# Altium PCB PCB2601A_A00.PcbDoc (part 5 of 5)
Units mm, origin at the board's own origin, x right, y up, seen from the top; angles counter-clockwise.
Board outline 30.4 x 51 mm, 8 copper layers (Top Layer, Signal Layer 2, Signal Layer 3, Signal Layer 4, Signal Layer 5, Signal Layer 6, Signal Layer 7, Bottom Layer), stack 1.492 mm thick; 194 components, 130 nets, 5039 pads, 478 vias.
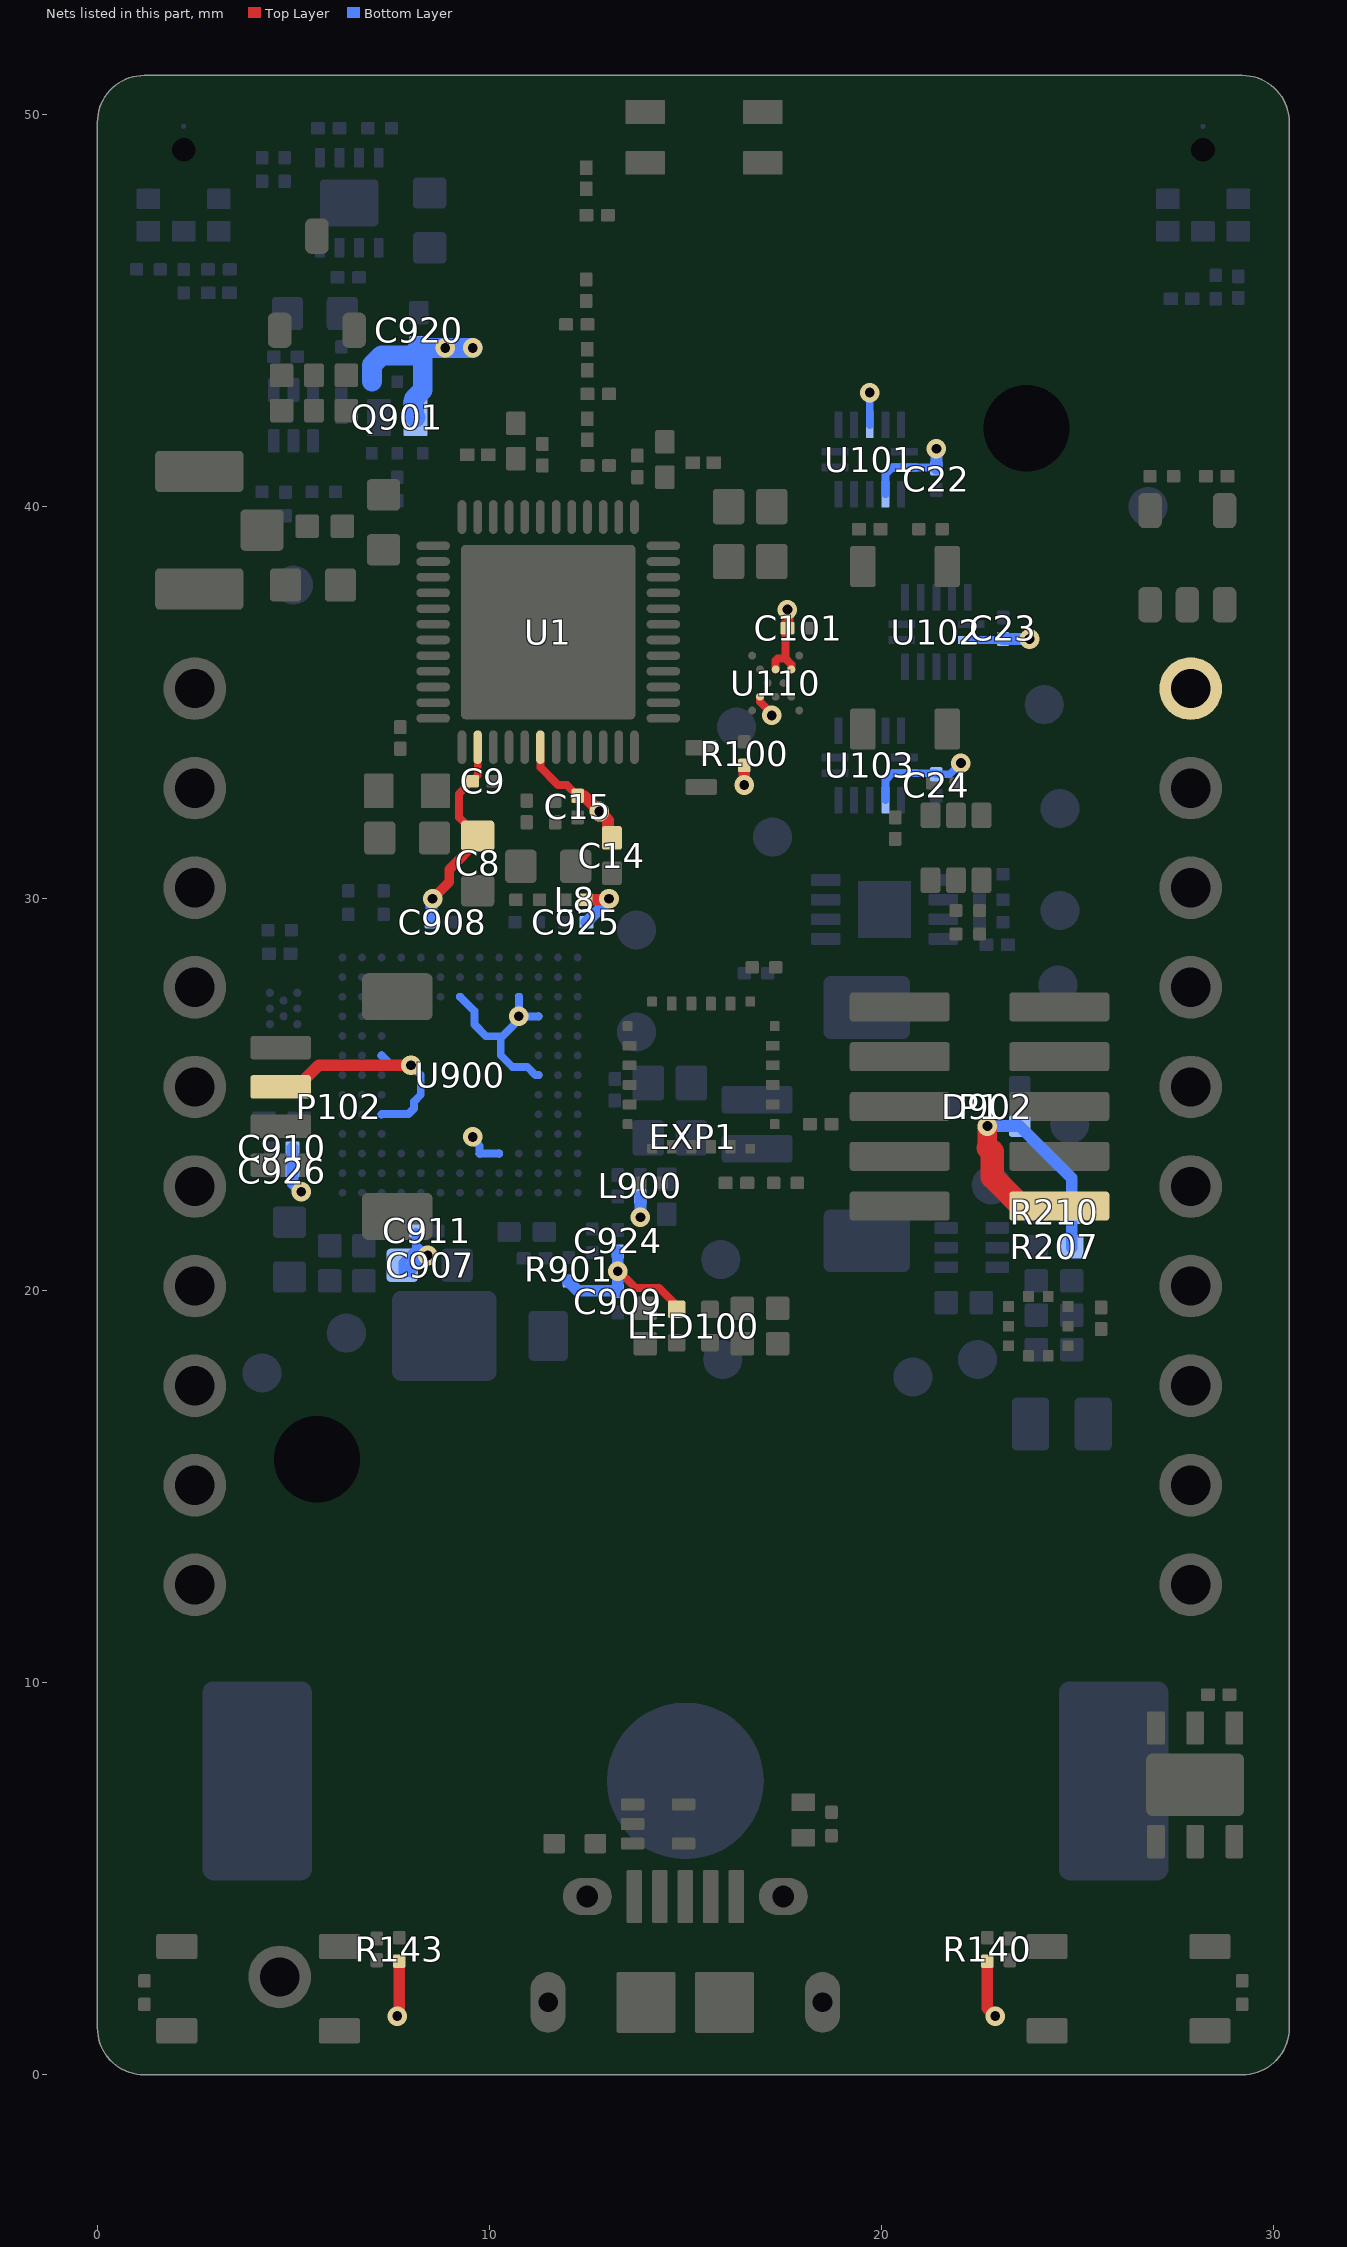
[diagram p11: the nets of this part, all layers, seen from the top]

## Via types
v1: diameter 0.5, hole 0.25, Top Layer to Bottom Layer, tented both sides, 478 vias

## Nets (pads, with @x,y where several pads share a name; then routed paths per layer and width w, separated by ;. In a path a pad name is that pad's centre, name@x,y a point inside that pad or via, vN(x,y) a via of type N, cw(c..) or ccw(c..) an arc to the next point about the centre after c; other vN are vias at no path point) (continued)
VMCU: C8.1 C9.1 C14.1 C15.1 C22.1 C23.1 C24.1 C101.1 C907.1 C908.1 C909.1 C910.1 C911.1 C920.1 C924.1 C925.1 C926.1 D902.2 EXP1.2 L8.1 L900.1 LED100.1 P1.1 P102.2 Q901.4 Q901.6 Q901.7 R100.1 R140.1 R143.1 R207.2 R210.2 R901.2 U1.38 U1.42 U101.2 U101.10 U101.14 U102.14 U103.2 U103.14 U110.B2 U110.D2 U110.F4 U900.C6 U900.C9 U900.G3 U900.H11 U900.J11 U900.K3 U900.L4 U900.L7 | length 58.6
  Top Layer w0.2: C8.1@9.7,31.6 9.225,32.075 9.225,32.675 C9.1@9.55,33 9.7,33.15 U1.38@9.7,33.865 ; U1.42@11.3,33.865 11.3,33.35 11.75,32.9 11.975,32.9 C15.1@12.25,32.625 ; v1@13.4,20.4 13.725,20.075 14.323,20.075 14.775,19.623 LED100.1@14.775,19.525 ; U110.F4@16.9,35.15 16.9,35.025 17.2,34.725 v1(17.2,34.675) ; U110.D2@17.3,35.85 17.3,36.075 17.35,36.125 17.55,36.125 ; C101.1@17.6,36.9 17.55,36.85 17.55,36.125 ; U110.B2@17.7,35.85 17.7,35.975 17.55,36.125
  Top Layer w0.25: v1(8.55,30) 8.975,30.425 8.975,30.75 9.7,31.475 C8.1@9.7,31.6
  Top Layer w0.3: P102.2@4.675,25.2 5.1,25.2 5.65,25.75 v1(8,25.75) ; v1(7.65,1.5) 7.7,1.55 R143.1@7.7,2.9 ; C15.1@12.25,32.625 12.4,32.625 v1(12.8,32.225) 13.025,32 13.025,31.65 C14.1@13.125,31.55 ; L8.1@12.445,29.975 13.025,29.975 v1(13.05,30) ; v1(16.5,32.9) R100.1@16.5,33.4 ; C101.1@17.6,36.9 v1(17.6,37.375) ; R140.1@22.7,2.9 22.7,1.7 v1(22.9,1.5)
  Top Layer w0.5: v1(22.7,24.2) 22.7,23.675 22.725,23.65
  Top Layer w0.6: 22.725,23.65 22.825,23.55 22.825,22.9 23.565,22.16 P1.1@24.535,22.16
  Bottom Layer w0.2: U900.C9@7.25,24.5 7.26,24.51 7.935,24.51 8.075,24.65 8.075,24.825 8.25,25 8.25,25.5 v1(8,25.75) 7.5,25.75 U900.C6@7.25,26 ; C907.1@8.125,20.825 8.125,21.075 ; C911.1@8.125,21.5 8.125,21.175 ; U900.G3@9.25,27.5 9.617,27.133 9.617,26.79 9.915,26.492 10.335,26.492 ; v1(9.575,23.925) 9.575,23.87 9.75,23.695 U900.H11@9.75,23.5 U900.J11@10.25,23.5 ; U900.K3@10.75,27.5 v1(10.75,27) ; U900.L7@11.25,25.5 11.175,25.5 10.964,25.712 10.584,25.712 10.287,26.009 10.287,26.443 10.335,26.492 ; U900.L4@11.25,27 v1(10.75,27) ; U101.10@19.7,42.085 v1(19.7,42.91) ; U103.2@20.1,32.515 20.1,33.025 20.275,33.2 U103.14@20.585,33.2 21.375,33.2 C24.1@21.4,33.175 21.741,33.175 v1(22.026,33.46) 22.011,33.475 22,33.475 v1@21.9,33.375 ; U101.2@20.1,40.315 20.1,40.825 20.275,41 U101.14@20.585,41 21.375,41 C22.1@21.4,40.975 ; U102.14@22.285,36.6 23.075,36.6 C23.1@23.1,36.625 ; C907.1@7.775,20.45 7.775,20.725 8.125,21.075 ; C907.1@7.775,20.45 7.975,20.45 v1(8.425,20.9) v1@8.4,20.9 ; C907.1@7.775,20.45 8.225,20.9 v1@8.4,20.9 ; 8.125,21.075 8.125,21.175 ; 8.125,21.175 v1@8.4,20.9 ; 10.335,26.492 10.633,26.79 10.633,26.883 v1(10.75,27)
  Bottom Layer w0.3: C910.1@4.975,23.65 C926.1@4.975,23.05 4.975,22.75 v1(5.2,22.525) ; C908.1@8.525,29.4 8.525,29.975 v1(8.55,30) ; R901.2@12,20.25 12.25,20 C909.1@13.275,20 v1(13.275,20.5) C924.1@13.275,21 ; C925.1@12.475,29.4 13.05,29.975 v1(13.05,30) ; v1(13.85,21.875) L900.1@13.85,22.405 ; C22.1@21.4,40.975 v1(21.4,41.475) v1@21.4,41.479 ; v1(22.7,24.2) D902.2@23.525,24.2 24.85,22.875 R210.2@24.85,22 24.85,21.95 R207.2@24.85,21.125 R207.2@24.85,21.1 ; C23.1@23.1,36.625 v1@23.604,36.625
  Bottom Layer w0.305: C909.1@13.275,19.98 C909.1@13.278,19.983
  Bottom Layer w0.508: Q901.4@7,43.188 7,43.608 7.242,43.85 8,43.85 C920.1@8.2,44.05 ; Q901.7@8.116,42.275 8.075,42.316 8.075,42.75 8.3,42.975 Q901.6@8.3,43.188 8.3,43.908 C920.1@8.2,44.008 ; C920.1@8.2,44.092 C920.1@8.2,44.05 ; v1(9.575,44.05) v1(8.875,44.05) C920.1@8.2,44.05
  other v1: 23.775,36.625
pads on no net: D101.3 D900.1 LOGO_SEGGER.1 M900.7 M900.9 M901.1 M902.1 P102.5 P102.6 P900.4 U104.1 U104.2 U104.3 U104.4 U104.5 U104.6 U104.7 U104.14 U104.15 U104.16 U104.17 U104.19 U104.20 U104.21 U105.4 U108.3 U108.4 U108.7 U110.A1 U110.A5 U110.G1 U110.G5 U111.H1 U112.H1 U900.A7 U900.B4 U900.B5 U900.B6 U900.B7 U900.B8 U900.B9 U900.B11 U900.C4 U900.C7 U900.D2 U900.D13 U900.E2 U900.E11 U900.E12 U900.E13 U900.F1 U900.F2 U900.F3 U900.F11 U900.F12 U900.G1 U900.G2 U900.G12 U900.H1 U900.H2 U900.J1 U900.J2 U900.K1 U900.K2 U900.K13 U900.L3 U900.L11 U900.L12 U900.L13 U900.M2 U900.M3 U900.M4 U900.M5 U900.M6 U900.M12 U900.M13 U900.N3 U900.N4 U900.N5 U900.N6 U900.N7 U901.C1 U902.8 U903.9

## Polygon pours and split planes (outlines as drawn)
GND on Top Layer "GND_L01_P047" (solid, remove dead copper, pour order 47): 0,0 0,51 30.4,51 30.403,0
GND on Bottom Layer "GND_L08_P053" (solid, remove dead copper, pour order 53): 0,0 0,51 30.4,51 30.403,0
VMCU on Signal Layer 7 "VMCU_L07_P052" (solid, remove dead copper, pour order 52): 0,0 0,51 30.4,51 30.403,0
GND on Signal Layer 6 "GND_L06_P051" (solid, remove dead copper, pour order 51): 0,0 0,51 30.4,51 30.403,0
GND on Signal Layer 5 "GND_L05_P050" (solid, remove dead copper, pour order 50): 0,0 0,51 30.4,51 30.403,0
GND on Signal Layer 4 "GND_L04_P049" (solid, remove dead copper, pour order 49): 0,0 0,51 30.4,51 30.403,0
GND on Signal Layer 3 "GND_L03_P048" (solid, remove dead copper, pour order 48): 0,0 0,51 30.4,51 30.403,0
GND on Signal Layer 2 "GND_L02_P024" (solid, remove dead copper, pour order 24): 0,0 0,51 30.4,51 30.403,0

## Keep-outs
Top Layer:
  circle w0.05: c5.6,15.7 r3
  circle w0.05: c23.7,42 r3
Bottom Layer:
  circle w0.1: c26.05,22 r0.5
  circle w0.1: c23.65,26.75 r0.5
  circle w0.1: c17.22,29.05 r0.5
  circle w0.1: c14.69,31.53 r0.5
  circle w0.1: c13.8,33.9 r0.5
  circle w0.1: c1.54,10.95 r0.5
  circle w0.1: c22.045,42.635 r0.3

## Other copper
Top Layer:
  pour cut-out: 13.876,42.87 ccw(c13.482,42.87) 13.482,43.264 ccw(c13.482,42.87) 13.089,42.87 ccw(c13.482,42.87) 13.482,42.477 ccw(c13.482,42.87)
  pour cut-out: 13.526,43.245 ccw(c13.132,43.245) 13.132,43.639 ccw(c13.132,43.245) 12.738,43.245 ccw(c13.132,43.245) 13.132,42.851 ccw(c13.132,43.245)
  pour cut-out: 13.526,42.495 ccw(c13.132,42.495) 13.132,42.889 ccw(c13.132,42.495) 12.738,42.495 ccw(c13.132,42.495) 13.132,42.101 ccw(c13.132,42.495)
  pour cut-out: 11.021,44.699 ccw(c11.414,44.699) 11.414,44.306 ccw(c11.414,44.699) 11.808,44.699 ccw(c11.414,44.699) 11.414,45.093 ccw(c11.414,44.699)
  pour cut-out: 11.404,44.32 ccw(c11.797,44.32) 11.797,43.927 ccw(c11.797,44.32) 12.191,44.32 ccw(c11.797,44.32) 11.797,44.714 ccw(c11.797,44.32)
  pour cut-out: 11.413,44.994 ccw(c11.807,44.994) 11.807,44.601 ccw(c11.807,44.994) 12.201,44.994 ccw(c11.807,44.994) 11.807,45.388 ccw(c11.807,44.994)
  pour cut-out: 8.5,34.8 8.5,33.9 7.9,33.3 6.6,33.3 6.6,31.096 9.325,31.096 9.325,34.8
  pour cut-out: 13.7,34.8 16.2,34.8 16.2,32.4 13.712,32.4 13.712,34.496
  region net N17172364: 8.25,32.5 8.25,33.275 9.25,34.275 9.325,34.275 9.4,34.2 9.4,33.5 9,33.1 9,32.5
  pour cut-out: 13.425,39.8 11.8,39.8 11.8,41.984 12.009,42.193 12.009,46.1 12.916,46.1 12.992,46.023 12.992,41.958 13.075,41.875 13.3,41.875 13.425,41.75
  pour cut-out: 16.35,40.55 18.3,40.55 18.3,39.9 17.805,39.405 17.806,37.94 14.6,37.94 14.6,38.8
  region net GND: 13.472,50.404 12.85,50.404 12.85,49.579 13.472,49.579
Bottom Layer:
  pour cut-out: 17.907,1.563 17.907,2.148 cw(c18.489,2.148) 18.489,2.731 cw(c18.489,2.15) 19.07,2.15 19.07,1.5 cw(c18.52,1.5) 18.52,0.95 cw(c18.52,1.563)
  pour cut-out: 10.907,1.563 10.907,2.148 cw(c11.489,2.148) 11.489,2.731 cw(c11.489,2.15) 12.07,2.15 12.07,1.5 cw(c11.52,1.5) 11.52,0.95 cw(c11.52,1.563)
  pour cut-out: 16.745,4.55 cw(c17.345,4.55) 17.345,5.15 17.645,5.15 cw(c17.645,4.55) 18.245,4.55 cw(c17.645,4.55) 17.645,3.95 17.345,3.95 cw(c17.345,4.55)
  pour cut-out: 11.745,4.55 cw(c12.345,4.55) 12.345,5.15 12.645,5.15 cw(c12.645,4.55) 13.245,4.55 cw(c12.645,4.55) 12.645,3.95 12.345,3.95 cw(c12.345,4.55)
  pour cut-out: 5.784,22.1 12.7,22.1 12.7,28.9 5.833,28.9
  pour cut-out: 7.75,45.65 7.975,45.65 7.975,45.15 7.75,45.15
  pour cut-out: 4.4,20.95 4.4,21.85 5.35,21.85 5.35,20.95
Multi-Layer:
  pour cut-out: 23,4.9 23,10.2 cw(c24.5,10.2) 24.5,11.7 31.3,11.7 31.3,3.4 24.5,3.4 cw(c24.5,4.9)
  pour cut-out: 17.475,51 17.475,44.4 13.475,44.4 13.475,51

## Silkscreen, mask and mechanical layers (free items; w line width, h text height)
Top Overlay:
  the board outline again, w0.1
Bottom Overlay:
  the board outline again, w0.1
Top Solder:
  the board outline again, w0.8
Bottom Solder:
  the board outline again, w0.8
BOARD OUTLINE 1:
  lines w0.1: 0,16.5 ccw(c-1.2,16.5) -2.4,16.5 -2.4,1.2 ccw(c1.2,1.2) 1.2,-2.4 29.2,-2.4 ccw(c29.2,1.2) 32.8,1.2 32.8,16.5 ccw(c31.6,16.5) 30.4,16.5 ; 0,28.5 cw(c-1.2,28.5) -2.4,28.5 -2.4,49.8 cw(c1.2,49.8) 1.2,53.4 9.21,53.4 cw(c9.21,52.2) 9.21,51 ; 21.19,51 cw(c21.19,52.2) 21.19,53.4 29.2,53.4 cw(c29.2,49.8) 32.8,49.8 32.8,28.499 ; 30.4,28.5 ccw(c31.6,28.5) 32.8,28.5 ; 0,1.2 ccw(c1.2,1.2) 1.2,0 29.2,0 ccw(c29.2,1.2) 30.4,1.2 30.4,49.8 ccw(c29.2,49.8) 29.2,51 1.2,51 ccw(c1.2,49.8) 0,49.8 0,1.2 ; 23.4,5.3 ccw(c23.8,5.3) 23.8,4.9 ccw(c23.8,5.3) 24.2,5.3 24.2,9.8 ccw(c23.8,9.8) 23.8,10.2 ccw(c23.788,9.812) 23.4,9.825 23.4,5.3 ; 25.2,4.3 ccw(c25.588,4.288) 25.575,3.9 29.2,3.9 ccw(c29.2,4.3) 29.6,4.3 ccw(c29.2,4.3) 29.2,4.7 25.6,4.7 ccw(c25.6,4.3) 25.2,4.3 ; 25.2,10.8 cw(c25.6,10.8) 25.6,11.2 29.2,11.2 cw(c29.2,10.8) 29.6,10.8 cw(c29.2,10.8) 29.2,10.4 25.575,10.4 cw(c25.588,10.788) 25.2,10.8
  text "Milling 0.8 mm (3 pcs)" at 14.6,2.7 h0.76
Mechanical 2:
  lines w0.1: 0,1.2 ccw(c1.2,1.2) 1.2,0 29.2,0 ccw(c29.2,1.2) 30.4,1.2 30.4,47.8 ccw(c29.2,47.8) 29.2,49 1.2,49 ccw(c1.2,47.8) 0,47.8 0,1.2
Mechanical 3:
  the board outline again, w0.1
Mechanical 15:
  lines w0.1: -0.5,0 0.5,0 ; 0,-0.5 0,0.5
Top EXT_SILKP 21/EXT_SILKS 22:
  text "ADC" at 1.424,42.194 h1.27
  text "1" at 0.7,34.885 h1.5
  text "2" at 29,34.86 h1.5
  text "RESET" at 23.306,34.566 h1.27 r90
  text "3" at 0.7,32.335 h1.5
  text "4" at 29,32.312 h1.5
  text "5" at 0.7,29.76 h1.5
  text "6" at 29,29.772 h1.5
  text "EFR32MG24" at 6.319,28.411 h2
  text "8" at 29,27.235 h1.5
  text "7" at 0.7,27.21 h1.5
  text "9" at 0.7,24.735 h1.5
  text "10" at 28.7,24.735 h1.5
  text "12" at 28.7,22.21 h1.5
  text "11" at 0.425,22.135 h1.5
  text "2" at 19.961,20.793 h1.27
  text "1" at 24.15,20.793 h1.27
  text "14" at 28.7,19.635 h1.5
  text "13" at 0.4,19.56 h1.5
  text "16" at 28.7,17.11 h1.5
  text "LED0" at 13.85,17.099 h1.27
  text "15" at 0.4,17.06 h1.5
  text "18" at 28.725,14.56 h1.5
  text "17" at 0.4,14.51 h1.5
  text "20" at 28.625,12.06 h1.5
  text "19" at 0.4,12.01 h1.5
  text "J-Link" at 16.504,7.601 h1.27
  text "BTN1" at 6.896,1.793 h1.27
  text "BTN0" at 20.819,1.799 h1.27
Bottom EXT_SILKP 21/EXT_SILKS 22:
  circle w0.152: c4.65,2.5 r0.966
  lines w0.152: 11,45.235 11,44.235 12,44.235 ; 11,47.285 11,48.285 12,48.285 ; 20.5,44.235 21.5,44.235 21.5,45.235 ; 20.5,48.285 21.5,48.285 21.5,47.285
  text "PCB2601A Rev A00" at 28.975,11.5 h1.5 r270
Mechanical 26:
  lines w0.2: -119.609,-49.807 -114.609,-49.807 ; -119.609,-2.807 -114.609,-2.807 ; -119.597,44.193 -114.609,44.193 ; -48.401,-96.838 -48.401,-91.838 ; -48.401,88.162 -48.401,93.162 ; 22.899,-96.838 22.899,-91.838 ; 22.899,88.162 22.899,93.162 ; 94.099,-96.838 94.099,-91.838 ; 94.099,88.162 94.099,93.162 ; 160.391,-49.807 165.391,-49.807 ; 160.391,-2.807 165.391,-2.807 ; 160.391,44.193 165.379,44.193 ; -119.597,-96.838 -119.597,93.154 165.391,93.154 165.391,-96.838 -119.597,-96.838 ; -114.609,-91.838 -114.609,88.162 160.391,88.162 160.391,-91.838 -114.609,-91.838
  text "1" at -86.709,89.733 h1.52
  text "2" at -14.401,89.733 h1.52
  text "3" at 58.199,89.733 h1.52
  text "4" at 128.999,89.733 h1.52
  text "D" at 162.389,70.593 h1.52
  text "D" at -117.722,69.388 h1.52
  text "C" at -117.722,21.893 h1.52
  text "C" at 162.262,21.893 h1.52
  text "B" at -117.722,-25.707 h1.52
  text "B" at 162.262,-25.707 h1.52
  text "A" at -117.722,-73.207 h1.52
  text "A" at 162.262,-73.207 h1.52
  text "1" at -85.489,-95.28 h1.52
  text "2" at -14.401,-95.28 h1.52
  text "3" at 57.899,-95.28 h1.52
  text "4" at 128.599,-95.28 h1.52
Mechanical 27:
  circle w0.152: c76.327,-70.307 r0.762
  circle w0.152: c76.327,-70.307 r1.778
  circle w0.254: c44.343,-84.764 r2.962
  lines w0.152: 65.329,-70.307 72.695,-70.307 ; 74.041,-70.307 78.613,-70.307 ; 66.091,-71.069 71.908,-72.085 71.933,-68.529 66.091,-69.545 66.091,-71.069
  lines w0.2: 40.294,-91.698 40.294,-64.838 80.308,-64.838 ; 40.294,-77.474 160.259,-77.474 ; 40.308,-73.838 80.308,-73.838 ; 60.589,-91.647 60.589,-77.55 ; 60.589,-73.791 60.589,-64.875 ; 140.308,-77.448 140.308,-73.838 ; 150.308,-73.838 150.308,-64.838 ; 160.308,-73.838 80.308,-73.838 ; 160.308,-64.838 80.308,-64.838 ; 80.308,-73.838 80.308,-64.838
  text "SIZE" at 42.308,-66.838 h1.52
  text "DOC NO" at 82.308,-66.838 h1.52
  text "REV" at 152.308,-66.838 h1.52
  text "PROJECTION" at 61.605,-67.187 h1.52
  text "A" at 152.029,-71.759 h2.54
  text "BRD2601A (PCB2601A Rev A00)" at 82.63,-72.2 h2.54
  text "A4" at 44.958,-72.212 h2.54
  text "REF" at 42.308,-75.838 h1.52
  text "SHEET" at 141.308,-75.838 h1.52
  text "1 of 2" at 151.15,-76.875 h1.52
  text "This drawing is confidential and is supplied on the express" at 61.072,-80.446 h1.52
  text "condition that it shall not be loaned, copied or disclosed to any" at 61.072,-82.986 h1.52
  text "other person or used for any purpose without the written consent of" at 61.072,-85.526 h1.52
  text "C" at 43.749,-85.78 h2.03
  text "2021" at 48.829,-85.932 h2.54
  text "SILICON LABS" at 61.503,-89.818 h2.54
Mechanical 28:
  lines w0.2: -119.609,-49.807 -114.609,-49.807 ; -119.609,-2.807 -114.609,-2.807 ; -119.597,44.193 -114.609,44.193 ; 160.391,-49.807 165.391,-49.807 ; 160.391,-2.807 165.391,-2.807 ; 160.391,44.193 165.391,44.193
  lines w0.203: -114.634,-91.838 -114.634,88.162 ; -114.609,-91.838 160.391,-91.838 160.391,88.162 -114.609,88.162 ; -48.401,-96.838 -48.401,-91.838 ; -48.401,88.162 -48.401,93.162 ; 22.899,-96.838 22.899,-91.838 ; 22.899,88.162 22.899,93.162 ; 94.099,-96.838 94.099,-91.838 ; 94.099,88.162 94.099,93.162 ; -119.597,-96.838 165.391,-96.838 165.391,93.154 -119.597,93.154 -119.597,-96.838
  text "4" at -85.693,89.733 h1.52
  text "3" at -13.385,89.733 h1.52
  text "2" at 59.215,89.733 h1.52
  text "1" at 130.015,89.733 h1.52
  text "D" at 163.405,70.593 h1.52
  text "D" at -116.706,69.388 h1.52
  text "C" at -116.706,21.893 h1.52
  text "C" at 163.405,20.293 h1.52
  text "B" at -116.706,-25.707 h1.52
  text "B" at 163.405,-26.807 h1.52
  text "A" at -116.706,-73.207 h1.52
  text "A" at 163.278,-73.207 h1.52
  text "4" at -84.473,-95.28 h1.52
  text "3" at -13.385,-95.28 h1.52
  text "2" at 58.762,-95.28 h1.52
  text "1" at 129.615,-95.28 h1.52
Mechanical 29:
  circle w0.152: c-30.531,-70.371 r0.762
  circle w0.152: c-30.531,-70.371 r1.778
  circle w0.254: c1.454,-84.828 r2.962
  lines w0.152: -32.817,-70.371 -28.245,-70.371 ; -26.899,-70.371 -19.533,-70.371 ; -26.137,-68.593 -26.111,-72.149 -20.295,-71.133 -20.295,-69.609 -26.137,-68.593
  lines w0.2: -114.512,-73.902 -34.512,-73.902 ; -114.512,-64.902 -34.512,-64.902 ; -114.462,-77.538 5.502,-77.538 ; -104.512,-73.902 -104.512,-64.902 ; -94.512,-77.513 -94.512,-73.902 ; -14.793,-91.711 -14.793,-77.614 ; -14.793,-73.855 -14.793,-64.94 ; 5.488,-73.902 -34.512,-73.902 ; 5.488,-64.902 -34.512,-64.902 ; 5.502,-91.762 5.502,-64.838 ; -34.512,-73.902 -34.512,-64.902
  text "REV" at -106.512,-66.902 h1.52
  text "DOC NO" at -36.512,-66.902 h1.52
  text "SIZE" at 3.488,-66.902 h1.52
  text "PROJECTION" at -15.809,-67.251 h1.52
  text "A" at -106.233,-71.823 h2.54
  text "BRD2601A" at -39.012,-72.276 h2.54
  text "A4" at 0.838,-72.276 h2.54
  text "SHEET" at -95.512,-75.902 h1.52
  text "REF" at 3.488,-75.902 h1.52
  text "2 of 2" at -105.2,-76.875 h1.52
  text "This drawing is confidential and is supplied on the express" at -15.275,-80.51 h1.52
  text "condition that it shall not be loaned, copied or disclosed to any" at -15.275,-83.05 h1.52
  text "other person or used for any purpose without the written consent of" at -15.275,-85.59 h1.52
  text "C" at 2.048,-85.844 h2.03
  text "2021" at -3.032,-85.996 h2.54
  text "SILICON LABS" at -15.707,-89.882 h2.54
Mechanical 30:
  lines w0.2: 40.294,-64.838 40.294,-43.998 160.294,-43.998 ; 40.294,-60.902 80.294,-60.902 ; 40.294,-56.902 80.294,-56.902 160.294,-56.903 ; 40.294,-52.902 80.294,-52.902 ; 80.294,-48.902 160.294,-48.902 ; 80.301,-64.838 80.301,-43.998
  text "CUSTOMER" at 81.403,-45.915 h1.27
  text "PROJECT NO" at 41.779,-46.931 h1.52
  text "SILICON LABS" at 99.183,-47.439 h2.03
  text "DRAWING TITLE" at 81.632,-50.843 h1.52
  text "BRD2601A" at 42.925,-51.25 h3.3
  text "DATE" at 41.779,-55.059 h1.52
  text "EFR32MG24 Dev Kit" at 84.807,-55.106 h2.03
  text ".Print_Date" at 60.067,-56.075 h1.52
  text "SHEET NAME" at 81.428,-58.996 h1.52
  text "DRAWN" at 41.779,-59.123 h1.52
  text "CHECK" at 41.779,-63.187 h1.52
